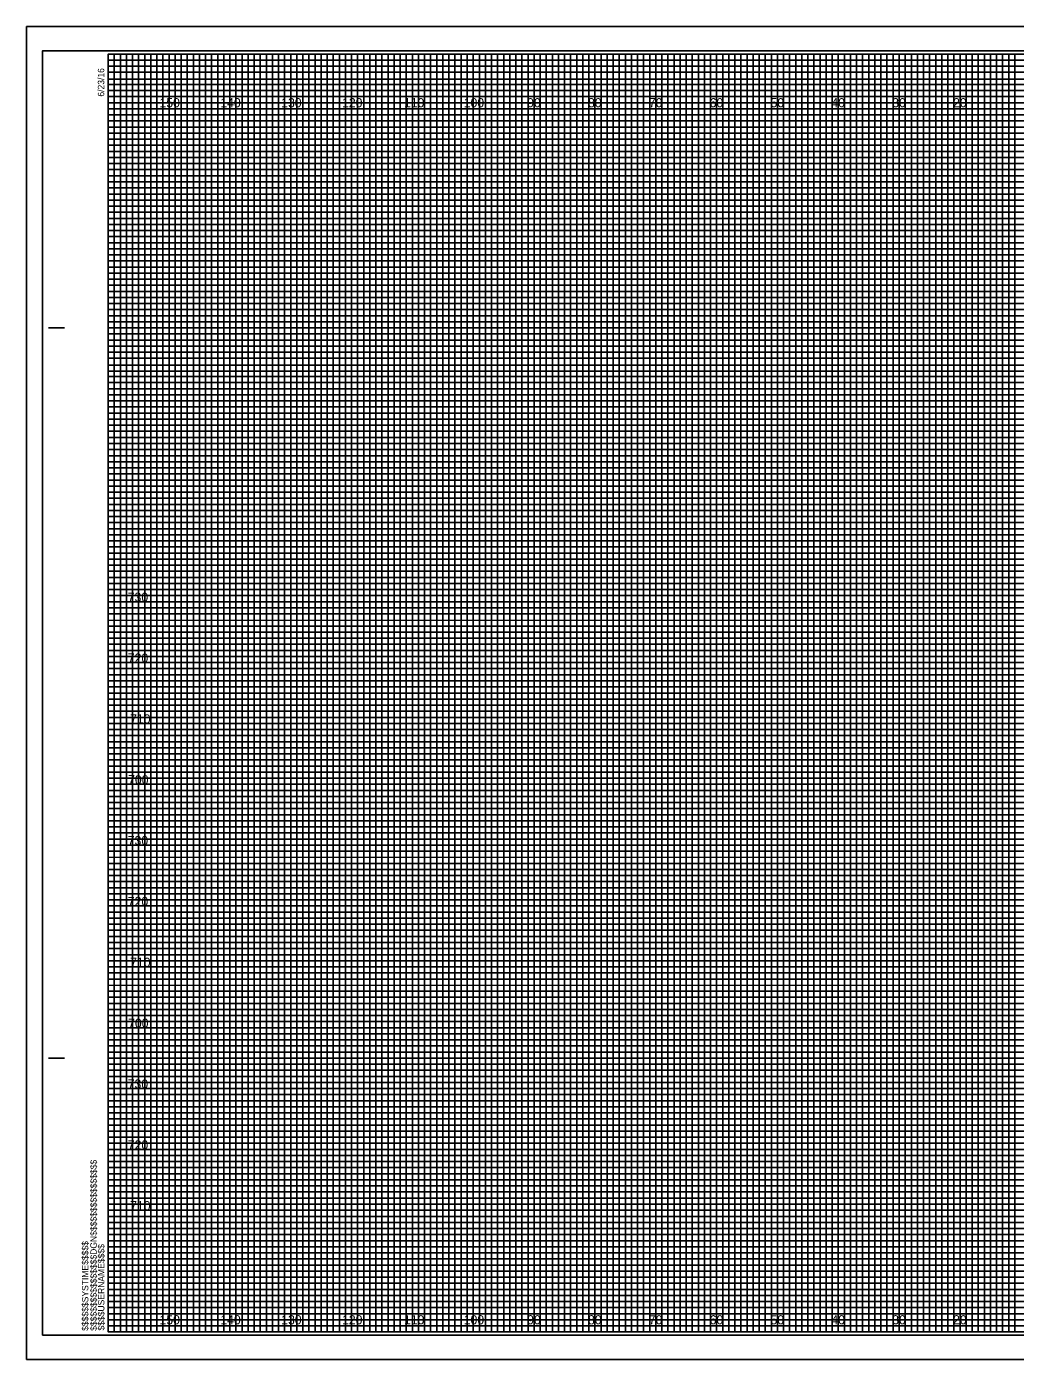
# Model space of a CAD drawing. Extents: x -98 to 717, y -10 to 1974.
# Drawn here: x -13.4 to 149.1, y 1755.5 to 1974.5 of the extents above; entities that cross this region are included whole.
import ezdxf

# ---------------------------------------------------------------- set-up
doc = ezdxf.new("R2010")
doc.units = 0
for name, color, linetype in [('Default', 7, 'Continuous'), ('Exist XS Center Line Elevation Label', 7, 'Continuous'), ('Prop CMT Conc Surface', 7, 'Continuous'), ('Prop CMT Concrete Structures', 7, 'Continuous'), ('Prop CMT Pvmt Course 1 CG', 7, 'Continuous'), ('Prop CMT Pvmt Course 2', 7, 'Continuous'), ('Prop CMT Pvmt Course 3', 7, 'Continuous'), ('Prop CMT Pvmt Surface', 7, 'Continuous'), ('Prop CMT Subgrade Earthwork', 7, 'Continuous'), ('Prop XS Earthwork Shape', 7, 'Continuous'), ('Prop XS Elevation Labels', 7, 'Continuous'), ('Typical Curb CELL', 7, 'Continuous')]:
    doc.layers.add(name, color=color, linetype=linetype)

msp = doc.modelspace()

# ---------------------------------------------------------------- linework, layer by layer
at = {"layer": 'Default'}
msp.add_lwpolyline([(323.3, 1755.5), (-13.4, 1755.5), (-13.4, 1974.5), (323.3, 1974.5)], close=True, dxfattribs=at)
at = {"layer": 'Exist XS Center Line Elevation Label'}
for p, q in [((0, 1969), (260, 1969)), ((260, 1967.98), (0, 1967.98)), ((0, 1967.98), (0, 1967)), ((0, 1967), (260, 1967)), ((260, 1965.89), (0, 1965.89)), ((0, 1965.89), (0, 1964)), ((0, 1964), (320, 1964))]:
    msp.add_line(p, q, dxfattribs=at)
for points in [[(0, 1963), (270, 1963), (320, 1963), (320, 1962), (0, 1962)], [(0, 1961), (320, 1961), (320, 1959), (0, 1959)], [(0, 1958), (320, 1958), (320, 1957), (0, 1956.98)], [(0, 1956), (320, 1956), (320, 1954), (0, 1954)], [(0, 1953), (320, 1953), (320, 1952), (0, 1952)], [(0, 1951), (320, 1951), (320, 1949), (0, 1949)], [(0, 1948), (320, 1948), (320, 1947), (0, 1947)], [(0, 1946), (320, 1946), (320, 1944), (0, 1944)], [(0, 1943), (320, 1943), (320, 1942), (0, 1942)], [(0, 1941), (320, 1941), (320, 1939), (0, 1939)], [(0, 1938), (320, 1938), (320, 1937), (0, 1937)], [(0, 1936), (320, 1936), (320, 1933.95), (320, 1933), (320, 1932), (0, 1932)], [(0, 1934), (320, 1934), (320, 1933), (0, 1933)], [(0, 1931), (320, 1931), (320, 1929), (0, 1929.03)], [(0, 1929.03), (320, 1929), (320, 1928), (0, 1928)], [(0, 1927), (320, 1927), (320, 1926), (0, 1926)], [(0, 1924), (320, 1924), (320, 1923), (0, 1923)], [(0, 1922), (320, 1922), (320, 1921), (0, 1921)], [(-0.07, 1918.89), (320, 1918.89), (320, 1917.88), (-0.07, 1917.88)], [(0, 1917), (320, 1917), (320, 1916), (0, 1916)], [(0, 1914), (320, 1914), (320, 1913), (0, 1913)], [(0, 1912), (320, 1912), (320, 1911), (0, 1911)], [(0, 1909), (320, 1909), (320, 1908), (0, 1908)], [(0, 1907), (320, 1907), (320, 1906), (0, 1906)], [(0, 1904), (320, 1904), (320, 1903), (0, 1903)], [(0, 1902), (320, 1902), (320, 1901), (0, 1901)], [(0, 1899), (320, 1899), (319.99, 1897.98), (0, 1898)], [(0, 1897), (320, 1897), (320, 1896), (0, 1896)], [(0, 1894), (320, 1894), (320, 1893), (0, 1893)], [(0, 1892), (320, 1892), (320, 1891), (0, 1891)], [(0, 1889), (320, 1889), (320, 1888), (0, 1888)], [(0, 1887), (320, 1887), (320, 1886), (0, 1886)], [(0, 1884), (320, 1884), (320, 1883), (0, 1883)], [(0, 1882), (320, 1882), (320, 1881), (0, 1881)], [(0, 1879), (320, 1879), (320, 1878), (0, 1878)], [(0, 1876.99), (320.07, 1876.91), (320, 1876), (0, 1876)], [(0, 1874), (320, 1874), (320, 1873), (0, 1873)], [(0, 1872), (320, 1872), (320, 1871), (0, 1871)], [(0, 1869), (320, 1869), (320, 1868), (0, 1868)], [(0, 1867), (320, 1867), (320, 1866), (0, 1866)], [(0, 1864), (320, 1864), (320, 1863), (0, 1863)], [(0, 1862), (320, 1862), (320, 1861), (0, 1861)], [(0, 1859), (320, 1859), (320, 1858), (0, 1858)], [(0, 1857), (320, 1857), (320, 1856), (0, 1856)], [(0, 1854), (320, 1854), (320, 1853), (0, 1853)], [(0, 1852), (320, 1852), (320, 1851), (0, 1851)], [(0, 1849), (320, 1849), (320, 1848), (0, 1848)], [(0, 1847), (320, 1847), (320, 1846), (0, 1846)], [(0, 1844), (320, 1844), (320, 1843), (0, 1843)], [(0, 1842), (320, 1842), (320, 1841), (0, 1841)], [(0, 1839), (320, 1839), (319.99, 1837.98), (0, 1838)], [(0, 1837), (320, 1837), (320, 1836), (0, 1836)], [(0, 1834), (320, 1834), (320, 1833), (0, 1833)], [(0, 1832), (320, 1832), (320, 1831), (0, 1831)], [(0, 1829), (320, 1829), (320, 1828), (0, 1828)], [(0, 1827), (320, 1827), (320, 1826), (0, 1826)], [(0, 1824), (320, 1824), (320, 1823), (0, 1823)], [(0, 1822), (320, 1822), (320, 1821), (0, 1821)], [(0, 1819), (320, 1819), (320, 1818), (0, 1818)], [(0, 1816.99), (320.07, 1816.91), (320, 1816), (0, 1816)], [(0, 1814), (320, 1814), (320, 1813), (0, 1813)], [(0, 1812), (320, 1812), (320, 1811), (0, 1811)], [(0, 1809), (320, 1809), (320, 1808), (0, 1808)], [(0, 1807), (320, 1807), (320, 1806), (0, 1806)], [(0, 1804), (320, 1804), (320, 1803), (0, 1803)], [(0, 1802), (320, 1802), (320, 1801), (0, 1801)], [(0, 1799), (320, 1799), (320, 1798), (0, 1798)], [(0, 1797), (320, 1797), (320, 1796), (0, 1796)], [(0, 1794), (320, 1794), (320, 1793), (0, 1793)], [(0, 1792), (320, 1792), (320, 1791), (0, 1791)], [(0, 1789), (320, 1789), (320, 1788), (0, 1788)], [(0, 1787), (320, 1787), (320, 1786), (0, 1786)], [(0, 1784), (320, 1784), (320, 1783), (0, 1783)], [(0, 1782), (320, 1782), (320, 1781), (0, 1781)], [(0, 1779), (320, 1779), (320, 1778), (0, 1778)], [(0, 1777), (320, 1777), (320, 1776), (0, 1776)], [(0, 1774), (320, 1774), (320, 1773), (0, 1773)], [(0, 1772), (320, 1772), (320, 1771), (0, 1771)], [(0, 1769), (320, 1769), (320, 1768), (0, 1768)], [(0, 1767), (320, 1767), (320, 1766), (0, 1766)], [(0, 1764), (320, 1764), (320, 1763), (0, 1763)], [(0, 1762), (320, 1762), (320, 1761), (0, 1761)]]:
    msp.add_lwpolyline(points, dxfattribs=at)
at = {"layer": 'Prop CMT Conc Surface'}
for p, q in [((-9.8, 1925), (-7.3, 1925)), ((-9.7, 1925), (-7.2, 1925)), ((-9.8, 1805), (-7.3, 1805)), ((-9.7, 1805), (-7.2, 1805)), ((0, 1760), (0, 1760)), ((0, 1760), (0, 1760)), ((0, 1760), (0, 1760)), ((0, 1760), (0, 1760)), ((0, 1760), (0, 1760)), ((0, 1760), (0, 1760)), ((0, 1760), (0, 1760))]:
    msp.add_line(p, q, dxfattribs=at)
msp.add_lwpolyline([(320, 1970), (0, 1970), (0, 1760), (320, 1760)], close=True, dxfattribs=at)
at = {"layer": 'Prop CMT Concrete Structures'}
for p, q in [((10, 1760), (10, 1970)), ((20, 1760), (20, 1970)), ((30, 1760), (30, 1970)), ((40, 1760), (40, 1970)), ((50, 1760), (50, 1970)), ((60, 1760), (60, 1970)), ((70, 1760), (70, 1970)), ((80, 1760), (80, 1970)), ((90, 1760), (90, 1970)), ((100, 1760), (100, 1970)), ((110, 1760), (110, 1970)), ((120, 1760), (120, 1970)), ((130, 1760), (130, 1970)), ((140, 1760), (140, 1970)), ((0, 1960), (320, 1960)), ((0, 1950), (320, 1950)), ((0, 1940), (320, 1940)), ((0, 1930), (320, 1930)), ((0, 1920), (320, 1920)), ((0, 1910), (320, 1910)), ((0, 1900), (320, 1900)), ((0, 1890), (320, 1890)), ((0, 1880), (320, 1880)), ((0, 1870), (320, 1870)), ((0, 1860), (320, 1860)), ((0, 1850), (320, 1850)), ((0, 1840), (320, 1840)), ((0, 1830), (320, 1830)), ((0, 1820), (320, 1820)), ((0, 1810), (320, 1810)), ((0, 1800), (320, 1800)), ((0, 1790), (320, 1790)), ((0, 1780), (320, 1780)), ((0, 1770), (320, 1770))]:
    msp.add_line(p, q, dxfattribs=at)
at = {"layer": 'Prop CMT Pvmt Course 2'}
msp.add_lwpolyline([(-13.4, 1755.5), (323.3, 1755.5), (323.3, 1974.5), (-13.4, 1974.5)], close=True, dxfattribs=at)
at = {"layer": 'Prop CMT Pvmt Course 3'}
msp.add_lwpolyline([(-10.8, 1759.5), (322.4, 1759.5), (322.4, 1970.5), (-10.8, 1970.5)], close=True, dxfattribs=at)
at = {"layer": 'Prop CMT Pvmt Surface'}
for p, q in [((323.3, 1974.5), (-13.4, 1974.5)), ((-13.4, 1974.5), (-13.4, 1755.5)), ((-13.4, 1755.5), (323.3, 1755.5))]:
    msp.add_line(p, q, dxfattribs=at)
at = {"layer": 'Prop CMT Subgrade Earthwork'}
for points in [[(0, 1760), (1, 1760), (1, 1970), (2, 1970), (2, 1760)], [(2, 1760), (3, 1760), (3, 1970), (4, 1970), (4, 1760)], [(5, 1760), (6, 1760), (6, 1970), (7, 1970), (7, 1760)], [(7, 1760), (8, 1760), (8, 1970), (9, 1970), (9, 1760)], [(10, 1760), (11, 1760), (11, 1970), (12, 1970), (12, 1760)], [(12, 1760), (13, 1760), (13, 1970), (14, 1970), (14, 1760)], [(15, 1760), (16, 1760), (16, 1970), (17, 1970), (17, 1760)], [(17, 1760), (18, 1760), (18, 1970), (19, 1970), (19, 1760)], [(20, 1760), (21, 1760), (21, 1970), (22, 1970), (22, 1760)], [(22, 1760), (23, 1760), (23, 1970), (24, 1970), (24, 1760)], [(25, 1760), (26, 1760), (26, 1970), (27, 1970), (27, 1760)], [(27, 1760), (28, 1760), (28, 1970), (29, 1970), (29, 1760)], [(30, 1760), (31, 1760), (31, 1970), (32, 1970), (32, 1760)], [(32, 1760), (33, 1760), (33, 1970), (34, 1970), (34, 1760)], [(35, 1760), (36, 1760), (36, 1970), (37, 1970), (37, 1760)], [(37, 1760), (38, 1760), (38, 1970), (39, 1970), (39, 1760)], [(40, 1760), (41, 1760), (41, 1970), (42, 1970), (42, 1760)], [(42, 1760), (43, 1760), (43, 1970), (44, 1970), (44, 1760)], [(45, 1760), (46, 1760), (46, 1970), (47, 1970), (47, 1760)], [(47, 1760), (48, 1760), (48, 1970), (49, 1970), (49, 1760)], [(50, 1760), (51, 1760), (51, 1970), (52, 1970), (52, 1760)], [(52, 1760), (53, 1760), (53, 1970), (54, 1970), (54, 1760)], [(55, 1760), (56, 1760), (56, 1970), (57, 1970), (57, 1760)], [(57, 1760), (58, 1760), (58, 1970), (59, 1970), (59, 1760)], [(60, 1760), (61, 1760), (61, 1970), (62, 1970), (62, 1760)], [(62, 1760), (63, 1760), (63, 1970), (64, 1970), (64, 1760)], [(65, 1760), (66, 1760), (66, 1970), (67, 1970), (67, 1760)], [(67, 1760), (68, 1760), (68, 1970), (69, 1970), (69, 1760)], [(70, 1760), (71, 1760), (71, 1970), (72, 1970), (72, 1760)], [(72, 1760), (73, 1760), (73, 1970), (74, 1970), (74, 1760)], [(75, 1760), (76, 1760), (76, 1970), (77, 1970), (77, 1760)], [(77, 1760), (78, 1760), (78, 1970), (79, 1970), (79, 1760)], [(80, 1760), (81, 1760), (81, 1970), (82, 1970), (82, 1760)], [(82, 1760), (83, 1760), (83, 1970), (84, 1970), (84, 1760)], [(85, 1760), (86, 1760), (86, 1970), (87, 1970), (87, 1760)], [(87, 1760), (88, 1760), (88, 1970), (89, 1970), (89, 1760)], [(90, 1760), (91, 1760), (91, 1970), (92, 1970), (92, 1760)], [(92, 1760), (93, 1760), (93, 1970), (94, 1970), (94, 1760)], [(95, 1760), (96, 1760), (96, 1970), (97, 1970), (97, 1760)], [(97, 1760), (98, 1760), (98, 1970), (99, 1970), (99, 1760)], [(100, 1760), (101, 1760), (101, 1970), (102, 1970), (102, 1760)], [(102, 1760), (103, 1760), (103, 1970), (104, 1970), (104, 1760)], [(105, 1760), (106, 1760), (106, 1970), (107, 1970), (107, 1760)], [(107, 1760), (108, 1760), (108, 1970), (109, 1970), (109, 1760)], [(110, 1760), (111, 1760), (111, 1970), (112, 1970), (112, 1760)], [(112, 1760), (113, 1760), (113, 1970), (114, 1970), (114, 1760)], [(115, 1760), (116, 1760), (116, 1970), (117, 1970), (117, 1760)], [(117, 1760), (118, 1760), (118, 1970), (119, 1970), (119, 1760)], [(120, 1760), (121, 1760), (121, 1970), (122, 1970), (122, 1760)], [(122, 1760), (123, 1760), (123, 1970), (124, 1970), (124, 1760)], [(125, 1760), (126, 1760), (126, 1970), (127, 1970), (127, 1760)], [(127, 1760), (128, 1760), (128, 1970), (129, 1970), (129, 1760)], [(130, 1760), (131, 1760), (131, 1970), (132, 1970), (132, 1760)], [(132, 1760), (133, 1760), (133, 1970), (134, 1970), (134, 1760)], [(135, 1760), (136, 1760), (136, 1970), (137, 1970), (137, 1760)], [(137, 1760), (138, 1760), (138, 1970), (139, 1970), (139, 1760)], [(140, 1760), (141, 1760), (141, 1970), (142, 1970), (142, 1760)], [(142, 1760), (143, 1760), (143, 1970), (144, 1970), (144, 1760)], [(145, 1760), (146, 1760), (146, 1970), (147, 1970), (147, 1760)], [(147, 1760), (148, 1760), (148, 1970), (149, 1970), (149, 1760)]]:
    msp.add_lwpolyline(points, dxfattribs=at)
at = {"layer": 'Prop XS Elevation Labels'}
for p, q in [((10, 1970), (0, 1970)), ((10, 1760), (10, 1970)), ((30, 1970), (20, 1970)), ((20, 1970), (20, 1760)), ((30, 1760), (30, 1970)), ((50, 1970), (40, 1970)), ((40, 1970), (40, 1760)), ((50, 1760), (50, 1970)), ((70, 1970), (60, 1970)), ((60, 1970), (60, 1760)), ((70, 1760), (70, 1970)), ((90, 1970), (80, 1970)), ((80, 1970), (80, 1760)), ((90, 1760), (90, 1970)), ((110, 1970), (100, 1970)), ((100, 1970), (100, 1760)), ((110, 1760), (110, 1970)), ((130, 1970), (120, 1970)), ((120, 1970), (120, 1760)), ((130, 1760), (130, 1970)), ((150, 1970), (140, 1970)), ((140, 1970), (140, 1760)), ((20, 1760), (10, 1760)), ((40, 1760), (30, 1760)), ((60, 1760), (50, 1760)), ((80, 1760), (70, 1760)), ((100, 1760), (90, 1760)), ((120, 1760), (110, 1760)), ((140, 1760), (130, 1760))]:
    msp.add_line(p, q, dxfattribs=at)
for points in [[(0, 1960), (320, 1960), (320, 1950), (0, 1950)], [(0, 1940), (320, 1940), (320, 1930), (0, 1930)], [(0, 1920), (320, 1920), (320, 1910), (0, 1910)], [(0, 1900), (320, 1900), (320, 1890), (0, 1890)], [(0, 1880), (320, 1880), (320, 1870), (0, 1870)], [(0, 1860), (320, 1860), (320, 1850), (0, 1850)], [(0, 1840), (320, 1840), (320, 1830), (0, 1830)], [(0, 1820), (320, 1820), (320, 1810), (0, 1810)], [(0, 1800), (320, 1800), (320, 1790), (0, 1790)], [(0, 1780), (320, 1780), (320, 1770), (0, 1770)]]:
    msp.add_lwpolyline(points, dxfattribs=at)
at = {"layer": 'Typical Curb CELL'}
for points in [[(0, 1970), (5, 1970), (5, 1760), (15, 1760), (15, 1970), (25, 1970), (25, 1760), (35, 1760), (35, 1970), (45, 1970), (45, 1760), (55, 1760), (55, 1970), (65, 1970), (65, 1760), (75, 1760), (75, 1970), (85, 1970), (85, 1760), (95, 1760), (95, 1970), (105, 1970), (105, 1760), (115, 1760), (115, 1970), (125, 1970), (125, 1760), (135, 1760), (135, 1970), (145, 1970), (145, 1760), (155, 1760)], [(0, 1965), (275, 1965)], [(0, 1945), (320, 1945), (320, 1955), (0, 1955)], [(0, 1925), (320, 1925), (320, 1935), (0, 1935)], [(0, 1905), (320, 1905), (320, 1915), (0, 1915)], [(0, 1885), (320, 1885), (320, 1895), (0, 1895)], [(0, 1865), (320, 1865), (320, 1875), (0, 1875)], [(0, 1845), (320, 1845), (320, 1855), (0, 1855)], [(0, 1825), (320, 1825), (320, 1835), (0, 1835)], [(0, 1805), (320, 1805), (320, 1815), (0, 1815)], [(0, 1785), (320, 1785), (320, 1795), (0, 1795)], [(0, 1765), (320, 1765), (320, 1775), (0, 1775)]]:
    msp.add_lwpolyline(points, dxfattribs=at)

# ---------------------------------------------------------------- texts
at = {"layer": 'Prop CMT Conc Surface'}
for s, p in [('6/23/16', (-0.65, 1963)), ('$$$$$$$$$$$$$$$$DGN$$$$$$$$$$$$$$$$', (-1.88, 1760.18)), ('$$$$$$SYSTIME$$$$$', (-3.26, 1760.18)), ('$$$$USERNAME$$$$', (-0.62, 1760.23))]:
    msp.add_text(s, height=1.05, rotation=90, dxfattribs=at).set_placement(p)
at = {"layer": 'Prop CMT Pvmt Course 1 CG'}
for s, p in [('730', (3.22, 1880)), ('720', (3.23, 1870)), ('710', (3.61, 1860)), ('700', (3.28, 1850)), ('730', (3.22, 1840)), ('720', (3.23, 1830)), ('710', (3.61, 1820)), ('700', (3.28, 1810)), ('730', (3.22, 1800)), ('720', (3.23, 1790)), ('710', (3.61, 1780))]:
    msp.add_text(s, height=1.5, dxfattribs=at).set_placement(p)
at = {"layer": 'Prop XS Earthwork Shape'}
for s, p in [('150', (8.44, 1961.25)), ('140', (18.44, 1961.25)), ('130', (28.44, 1961.25)), ('120', (38.44, 1961.25)), ('110', (48.62, 1961.25)), ('100', (58.44, 1961.25)), ('90', (68.86, 1961.25)), ('80', (78.86, 1961.25)), ('70', (88.86, 1961.25)), ('60', (98.86, 1961.25)), ('50', (108.86, 1961.25)), ('40', (118.86, 1961.25)), ('30', (128.86, 1961.25)), ('20', (138.86, 1961.25)), ('150', (8.44, 1761.25)), ('140', (18.44, 1761.25)), ('130', (28.44, 1761.25)), ('120', (38.44, 1761.25)), ('110', (48.62, 1761.25)), ('100', (58.44, 1761.25)), ('90', (68.86, 1761.25)), ('80', (78.86, 1761.25)), ('70', (88.86, 1761.25)), ('60', (98.86, 1761.25)), ('50', (108.86, 1761.25)), ('40', (118.86, 1761.25)), ('30', (128.86, 1761.25)), ('20', (138.86, 1761.25))]:
    msp.add_text(s, height=1.5, dxfattribs=at).set_placement(p)

doc.saveas('drawing.dxf')
